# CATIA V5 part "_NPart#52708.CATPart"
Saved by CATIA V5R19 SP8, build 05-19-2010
Part number: Pièce13
Revision: ANY
Definition: UNKNOWN
Nomenclature: Pièce13
Source: Unknown
Bounding box of the stored display mesh (mm): x -45.798 to -21.798, y 0 to 12, z -7.5 to 7.5
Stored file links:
  D:\Documents\1_Travail\1 - ac-limoges.fr\ac-limoges.fr\Emmanuel Maynard - STI2D_Turgot\2 -2I2D\2_SEQUENCE_Serrure_Biométrique\5-Spé_ITEC\Serrure_Bio_Eleve\_NPart#52708.CATPart
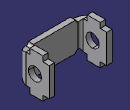
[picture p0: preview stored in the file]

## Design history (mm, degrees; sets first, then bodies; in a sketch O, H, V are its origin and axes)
Body1 "Symétrie8" (main body)
  Solid1: solid without history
